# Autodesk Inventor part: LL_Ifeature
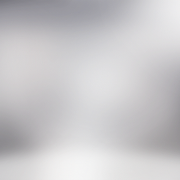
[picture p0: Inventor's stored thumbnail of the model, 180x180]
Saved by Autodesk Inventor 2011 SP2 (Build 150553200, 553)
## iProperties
Created: 2011-10
Part Number: LL_Ifeature
Material: S235JRG2
Document SubType Name: Modeling
Designer: SCHALLA
Density: 7.85 g/cm^3
MatBom2.0.1.: PS!Inventor!PV!15.0  SP: 1!AVMa!2!AVMi!0!AVBu!0
Author: SCHALLA
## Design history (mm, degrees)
sketch "Skizze2"
  geometry: C1 r 63 at (0, 0); 1 further point
  constraints: 1 centre point, 1 coincident
  dimensions: "d2" = 126 diameter of C1
extrude "RAW" new body sketch "Skizze2" distance "d3" = 10; taper "d4" = 0 deg
sketch "LL_SK" dims "LLTK" = 96
  geometry: L1 (0, 0)-(0, 48); L2 (-6.5, 58)-(6.5, 58); L3 (6.5, 58)-(6.5, 38); L4 (6.5, 38)-(-6.5, 38); L5 (-6.5, 38)-(-6.5, 58); L6 (0, 0)-(24, 41.569); L7 (0, 0)-(-24, 41.569); L8 (0, 0)-(46.364, 12.423); L9 (0, 0)-(36.77, -30.854); L10 (0, 0)-(4.183, -47.817); L11 (0, 0)-(-27.532, -39.319); L12 (0, 0)-(-47.271, -8.335); L13 (0, 0)-(-45.105, 16.417); L14 (23.371, 53.479)-(34.629, 46.979); L15 (13.371, 36.159)-(23.371, 53.479); L16 (24.629, 29.659)-(13.371, 36.159); L17 (34.629, 46.979)-(24.629, 29.659); L18 (18.371, 44.819)-(29.629, 38.319); L19 (29, 50.229)-(24, 41.569); L20 (3.312, -37.855)-(4.183, -47.817); L21 (-2.292, -48.384)-(10.659, -47.251); L22 (-1.42, -58.346)-(-3.163, -38.422); L23 (9.787, -37.289)-(11.53, -57.213); L24 (-3.163, -38.422)-(9.787, -37.289); L25 (11.53, -57.213)-(-1.42, -58.346); L26 (-33.485, 19.105)-(-37.931, 6.889); L27 (-37.931, 6.889)-(-56.725, 13.729); L28 (-47.328, 10.309)-(-42.882, 22.525); L29 (-54.502, 19.837)-(-45.105, 16.417); L30 (-52.279, 25.945)-(-33.485, 19.105); L31 (-56.725, 13.729)-(-52.279, 25.945); L32 (-55.99, -16.473)-(-58.248, -3.67); L33 (-58.248, -3.67)-(-38.551, -0.197); L34 (-48.399, -1.934)-(-46.142, -14.736); L35 (-37.423, -6.599)-(-47.271, -8.335); L36 (-36.294, -13)-(-55.99, -16.473); L37 (-38.551, -0.197)-(-36.294, -13); L38 (38.388, 3.557)-(35.023, 16.114); L39 (35.023, 16.114)-(54.341, 21.29); L40 (44.682, 18.702)-(48.047, 6.145); L41 (56.024, 15.012)-(46.364, 12.423); L42 (57.706, 8.733)-(38.388, 3.557); L43 (54.341, 21.29)-(57.706, 8.733); L44 (48.609, -32.302)-(40.252, -42.261); L45 (40.252, -42.261)-(24.932, -29.405); L46 (32.592, -35.833)-(40.948, -25.875); L47 (29.11, -24.426)-(36.77, -30.854); L48 (33.288, -19.447)-(48.609, -32.302); L49 (24.932, -29.405)-(33.288, -19.447); L50 (-27.943, -51.239)-(-38.592, -43.783); L51 (-38.592, -43.783)-(-27.12, -27.4); L52 (-32.856, -35.591)-(-22.207, -43.048); L53 (-21.796, -31.128)-(-27.532, -39.319); L54 (-16.471, -34.856)-(-27.943, -51.239); L55 (-27.12, -27.4)-(-16.471, -34.856); L56 (-13.371, 36.159)-(-24.629, 29.659); L57 (-24.629, 29.659)-(-34.629, 46.979); L58 (-29.629, 38.319)-(-18.371, 44.819); L59 (-29, 50.229)-(-24, 41.569); L60 (-23.371, 53.479)-(-13.371, 36.159); L61 (-34.629, 46.979)-(-23.371, 53.479); C1 r 63 at (0, 0) reference; 2 further points
  constraints: 122 end point, 34 midpoint, 17 perpendicular, 10 parallel, 1 coincident, 1 horizontal, 1 horizontal alignment, 1 vertical, 1 vertical alignment, 11 other
  dimensions: "LLB" = 13 distance between parallel lines of L3 L5; "LLH" = 20 distance of L4.end L2.start; "W_LL_END" = 30 deg angle of L1 L7; "W_LL_1" = 30 deg angle of L1 L6; "W_LL_2" = 45 deg angle of L8 L6; "W_LL_3" = 55 deg angle of L8 L9; "W_LL_4" = 45 deg angle of L10 L9; "W_LL_5" = 40 deg angle of L11 L10; "W_LL_6" = 45 deg angle of L11 L12; "W_LL_7" = 30 deg angle of L12 L13; "d20" = 13 distance between parallel lines of L17 L15; "d21" = 20 distance of L15.start L14.start; "d38" = 13 distance between parallel lines of L23 L22; "d39" = 20 distance of L22.start L22.end; "d44" = 13 distance between parallel lines of L30 L27; "d45" = 20 distance of L26.end L27.end; "d48" = 13 distance between parallel lines of L36 L33; "d49" = 20 distance of L32.end L33.end; "d50" = 13 distance between parallel lines of L42 L39; "d51" = 20 distance of L38.end L39.end; "d52" = 13 distance between parallel lines of L48 L45; "d53" = 20 distance of L44.end L45.end; "d54" = 13 distance between parallel lines of L54 L51; "d55" = 20 distance of L50.end L51.end; "d56" = 13 distance between parallel lines of L60 L57; "d57" = 20 distance of L56.end L57.end
extrude "LL_BASE" cut sketch "LL_SK" taper "d9" = 0 deg; distance "LL_T" = 10
fillet "LL_R_1" dims "LL_R_INNEN" = 6.5 (= 0.5 x LLB)
fillet "LL_R_2" dims "d61" = 0, "LL_R_AUSSEN" = 1, "LL_R_AUSSEN_AKT" = 10 [user parameter]
node "Volumenkörper2"
